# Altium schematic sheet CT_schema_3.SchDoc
size 362 x 192 mm
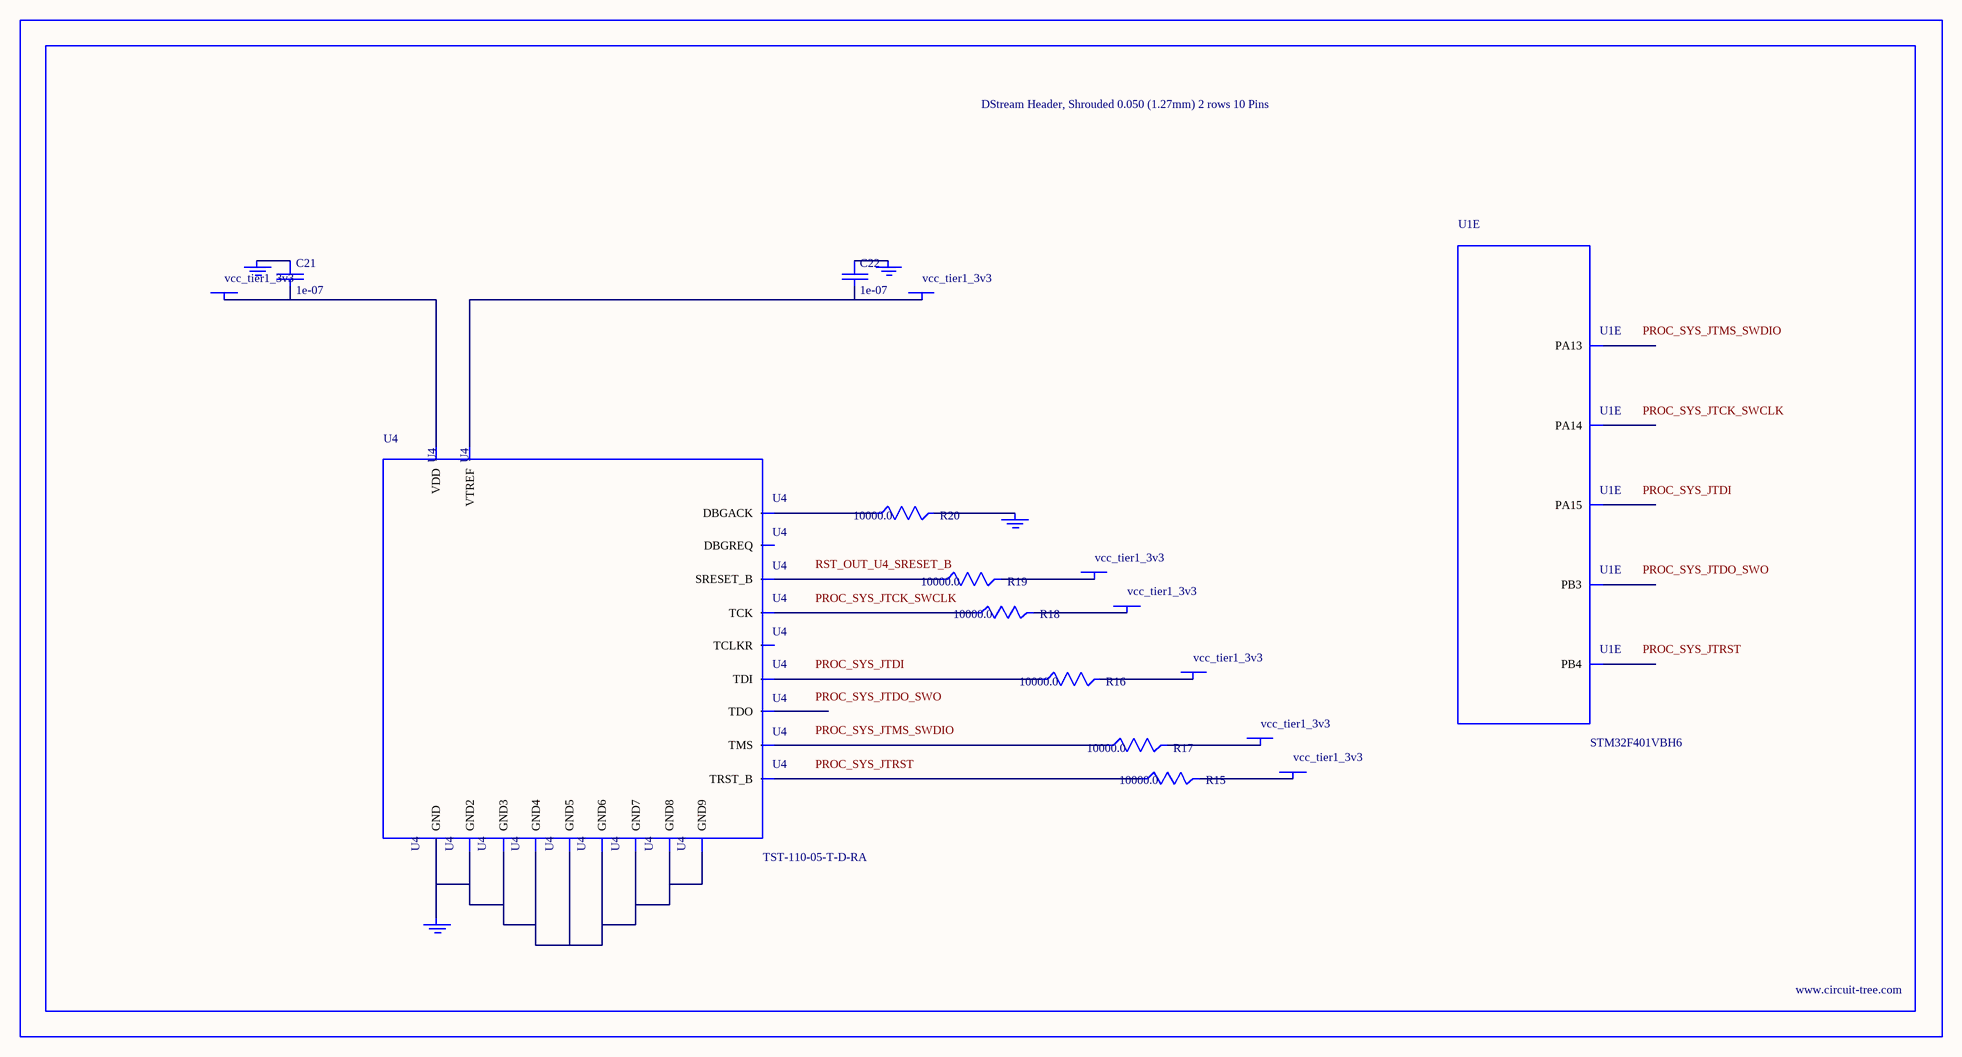
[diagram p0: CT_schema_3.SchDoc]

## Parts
BORDER2  (no value)
C21  1e-07  [C0402]
C22  1e-07  [C0402]
GND_INSTANCE_2_0  (no value)
GND_INSTANCE_2_1  (no value)
GND_INSTANCE_2_2  (no value)
GND_INSTANCE_2_3  (no value)
POWER_INSTANCE_2_0  vcc_tier1_3v3
POWER_INSTANCE_2_1  vcc_tier1_3v3
POWER_INSTANCE_2_2  vcc_tier1_3v3
POWER_INSTANCE_2_3  vcc_tier1_3v3
POWER_INSTANCE_2_4  vcc_tier1_3v3
POWER_INSTANCE_2_5  vcc_tier1_3v3
POWER_INSTANCE_2_6  vcc_tier1_3v3
R15  10000.0  [R0603]
R16  10000.0  [R0603]
R17  10000.0  [R0603]
R18  10000.0  [R0603]
R19  10000.0  [R0603]
R20  10000.0  [R0603]
U1  STM32F401VBH6  [UFBGA100]  (part E of 8)
U4  TST-110-05-T-D-RA  [TST-110-05-T-D-RA]

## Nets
NetC21_1: C21.1 GND_INSTANCE_2_1.0(GND)
NetC21_2: C21.2 POWER_INSTANCE_2_1.0(PWR) U4.2(VDD)
NetC22_1: C22.1 GND_INSTANCE_2_0.0(GND)
NetC22_2: C22.2 POWER_INSTANCE_2_0.0(PWR) U4.1(VTREF)
NetGND_INSTANCE_2_2_0: GND_INSTANCE_2_2.0(GND) R20.2
NetGND_INSTANCE_2_3_0: GND_INSTANCE_2_3.0(GND) U4.4(GND) U4.6(GND2) U4.8(GND3) U4.10(GND4) U4.12(GND5) U4.14(GND6) U4.16(GND7) U4.18(GND8) U4.20(GND9)
NetPOWER_INSTANCE_2_2_0: POWER_INSTANCE_2_2.0(PWR) R15.2
NetPOWER_INSTANCE_2_3_0: POWER_INSTANCE_2_3.0(PWR) R16.2
NetPOWER_INSTANCE_2_4_0: POWER_INSTANCE_2_4.0(PWR) R17.2
NetPOWER_INSTANCE_2_5_0: POWER_INSTANCE_2_5.0(PWR) R18.2
NetPOWER_INSTANCE_2_6_0: POWER_INSTANCE_2_6.0(PWR) R19.2
NetR15_1: R15.1 U4.3(TRST_B)
NetR16_1: R16.1 U4.5(TDI)
NetR17_1: R17.1 U4.7(TMS)
NetR18_1: R18.1 U4.9(TCK)
NetR19_1: R19.1 U4.15(SRESET_B)
NetR20_1: R20.1 U4.19(DBGACK)

Not connected (* = marked no-connect by the designer): U1 A7(PB4) A8(PB3) A9(PA15) A10(PA14) A11(PA13); U4 11(TCLKR) 13(TDO) 17(DBGREQ)

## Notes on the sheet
- Labels drawn without touching a wire or pin: PROC_SYS_JTCK_SWCLK, PROC_SYS_JTDI, PROC_SYS_JTDO_SWO, PROC_SYS_JTMS_SWDIO, PROC_SYS_JTRST, RST_OUT_U4_SRESET_B

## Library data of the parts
BORDER2 = BORDER_PAGE2
C21 C22 = C0402C104K3RACTU
GND_INSTANCE_2_0-GND_INSTANCE_2_3 = GND
POWER_INSTANCE_2_0-POWER_INSTANCE_2_6 = PWR
R15-R20 = RC0603JR-0710KL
